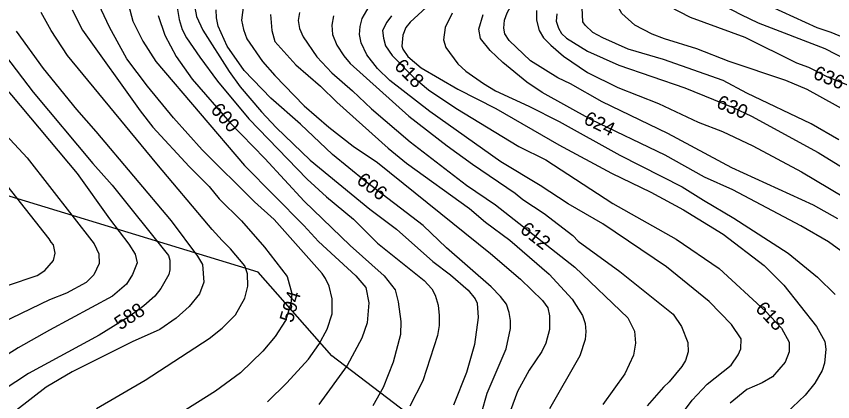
# Model space of a CAD drawing. Extents: x -709418 to -703832, y -1161719 to -1157826.
# Drawn here: x -708650.5 to -708183.3, y -1160344.3 to -1160123.5 of the extents above; entities that cross this region are included whole.
import ezdxf

# ---------------------------------------------------------------- set-up
doc = ezdxf.new("R2010")
doc.units = 0
for name, color, linetype in [('120_vrstevnice hlavní', 7, 'Continuous'), ('121_vrstevnice hlavní_popis', 7, 'Continuous'), ('122_vrstevnice základní', 7, 'Continuous'), ('606_RBC_návrh', 7, 'Continuous')]:
    doc.layers.add(name, color=color, linetype=linetype)

msp = doc.modelspace()

# ---------------------------------------------------------------- linework, layer by layer
at = {"layer": '120_vrstevnice hlavní'}
for points in [[(-708163.85, -1160141.12), (-708184.1, -1160132.87), (-708192.2, -1160130.12), (-708218.82, -1160117.98), (-708242.4, -1160104.52), (-708247.89, -1160100.04), (-708251.36, -1160096.42), (-708252.81, -1160093.82), (-708253.24, -1160088.32), (-708252.52, -1160080.22), (-708250.21, -1160068.07), (-708245.43, -1160051.87), (-708232.42, -1160023.52), (-708214.33, -1159987.07), (-708204.21, -1159962.77), (-708198.42, -1159946.57), (-708191.91, -1159933.41), (-708183.23, -1159919.09)], [(-708415.97, -1160118.55), (-708425.08, -1160126.8), (-708427.54, -1160129.83), (-708429.28, -1160134.32), (-708429.85, -1160140.54), (-708429.28, -1160142.42), (-708426.53, -1160146.47), (-708418.72, -1160153.12)], [(-708569.29, -1160123.04), (-708565.53, -1160134.32), (-708559.02, -1160146.47), (-708549.91, -1160159.49), (-708528.36, -1160184.37), (-708508.25, -1160204.91), (-708485.69, -1160229.5), (-708459.51, -1160254.81), (-708439.98, -1160272.17), (-708433.76, -1160280.27), (-708431.88, -1160287.06), (-708430.43, -1160298.35)], [(-708505.07, -1160122.46), (-708504.2, -1160131.72), (-708502.47, -1160137.94), (-708490.46, -1160151.39), (-708476.43, -1160163.54), (-708467.17, -1160172.65), (-708437.67, -1160199.12), (-708427.25, -1160207.65), (-708391.23, -1160233.55), (-708381.98, -1160241.5), (-708368.09, -1160251.77), (-708345.53, -1160271.3), (-708332.36, -1160285.62), (-708326.43, -1160294.88)], [(-708341.19, -1160122.17), (-708341.48, -1160126.22), (-708340.18, -1160130.27), (-708338.41, -1160133.4), (-708335.55, -1160136.06), (-708323.54, -1160143.43), (-708305.6, -1160151.53), (-708268, -1160164.55), (-708240.23, -1160175.69), (-708229.81, -1160180.75), (-708191.62, -1160201.58), (-708177.74, -1160210.11)], [(-708650.58, -1160132.01), (-708635.1, -1160153.41), (-708616.16, -1160176.84), (-708605.02, -1160189.43), (-708561.92, -1160240.78), (-708546.73, -1160261.03), (-708543.98, -1160265.66), (-708543.26, -1160275.93)], [(-708418.72, -1160153.12), (-708397.89, -1160165.27), (-708376.05, -1160176.41), (-708340.03, -1160197.09), (-708309.94, -1160213.44), (-708287.38, -1160224.29), (-708268.58, -1160234.41), (-708246.01, -1160248.44), (-708222.58, -1160266.24), (-708211.3, -1160277.66), (-708192.49, -1160301.24), (-708187.72, -1160309.92), (-708187.29, -1160314.26), (-708188.01, -1160322.36), (-708189.31, -1160326.41), (-708193.51, -1160333.78), (-708199, -1160340.58), (-708209.99, -1160351)], [(-708543.26, -1160275.93), (-708545.74, -1160282.61), (-708551.54, -1160289.71), (-708559.1, -1160296.56), (-708568.43, -1160302.92), (-708584.19, -1160310.06), (-708618.62, -1160327.28), (-708633.37, -1160336.1), (-708650.44, -1160349.12)], [(-708326.43, -1160294.88), (-708324.99, -1160299.5), (-708324.55, -1160304.13), (-708324.99, -1160308.76), (-708328.03, -1160318.02), (-708345.38, -1160348.39)], [(-708430.43, -1160298.35), (-708430.72, -1160305.87), (-708434.77, -1160321.78), (-708440.56, -1160336.24), (-708446.49, -1160346.8)]]:
    msp.add_lwpolyline(points, dxfattribs=at)
at = {"layer": '122_vrstevnice základní'}
for points in [[(-708324.99, -1160128.68), (-708326.29, -1160126.65), (-708326.72, -1160118.7), (-708322.09, -1160105.97), (-708283.19, -1160024.39), (-708273.06, -1160005.3), (-708264.96, -1159991.41), (-708253.24, -1159973.48), (-708243.99, -1159956.99), (-708227.35, -1159915.04), (-708205.08, -1159871.65), (-708199.44, -1159856.31), (-708195.1, -1159838.96), (-708193.94, -1159830.28), (-708193.51, -1159819), (-708194.81, -1159784.57), (-708194.52, -1159772.42), (-708191.91, -1159742.04), (-708187.14, -1159717.74), (-708182.08, -1159683.32)], [(-708177.88, -1159857.18), (-708185.84, -1159879.46), (-708196.11, -1159897.68), (-708210.72, -1159928.06), (-708226.05, -1159967.4), (-708230.82, -1159976.66), (-708253.1, -1160013.69), (-708268.29, -1160041.46), (-708273.2, -1160053.03), (-708282.17, -1160078.49), (-708286.8, -1160094.11), (-708288.1, -1160102.21), (-708287.23, -1160107.42), (-708285.64, -1160110.31), (-708282.03, -1160114.36), (-708276.97, -1160117.69), (-708264.82, -1160124.05), (-708233.57, -1160135.48), (-708204.07, -1160150.09), (-708197.12, -1160152.69), (-708186.71, -1160158.04), (-708169.35, -1160164.98)], [(-708172.68, -1160179.45), (-708197.85, -1160165.42), (-708210.14, -1160160.21), (-708242.54, -1160149.36), (-708261.06, -1160142.13), (-708279.57, -1160136.49), (-708286.51, -1160133.74), (-708296.49, -1160128.68), (-708303.87, -1160121.88), (-708306.76, -1160116.67), (-708307.78, -1160111.47), (-708307.2, -1160106.26), (-708304.59, -1160095.84), (-708300.98, -1160085.43), (-708294.61, -1160069.81), (-708275.09, -1160030.75), (-708254.69, -1159996.04), (-708236.47, -1159961.32), (-708226.77, -1159940.5), (-708219.25, -1159919.67)], [(-708130.59, -1160171.49), (-708187.58, -1160142.13), (-708225.76, -1160127.38), (-708235.74, -1160122.75), (-708249.19, -1160115.52), (-708261.05, -1160107.42), (-708266.7, -1160101.34), (-708269.01, -1160096.13), (-708269.3, -1160083.12), (-708266.41, -1160070.1), (-708257.58, -1160045.8), (-708251.36, -1160031.33), (-708246.59, -1160022.65), (-708228.22, -1159993.73)], [(-708731.58, -1160091.51), (-708729.7, -1160101.05), (-708725.65, -1160110.6), (-708715.09, -1160126.51), (-708696.29, -1160148.78), (-708644.22, -1160204.62), (-708605.89, -1160253.8), (-708603.28, -1160259.58), (-708603.14, -1160265.08), (-708606.18, -1160271.59), (-708610.52, -1160276.07), (-708621.8, -1160282.15), (-708631.49, -1160285.91), (-708658.83, -1160299.07), (-708666.64, -1160303.99), (-708679.94, -1160315.27), (-708697.16, -1160332.92), (-708715.24, -1160352.44)], [(-708180.34, -1160239.62), (-708194.23, -1160231.81), (-708241.09, -1160210.26), (-708277.54, -1160190.59), (-708315.15, -1160172.51), (-708333.38, -1160162.24), (-708340.61, -1160158.77), (-708356.23, -1160148.93), (-708368.53, -1160137.36), (-708370.86, -1160133.61), (-708371.56, -1160130.27), (-708371.13, -1160125.64), (-708369.68, -1160121.59), (-708365.2, -1160113.49), (-708352.33, -1160093.24)], [(-708506.81, -1160344.34), (-708495.67, -1160333.5), (-708483.37, -1160319.9), (-708477.3, -1160311.51), (-708472.67, -1160302.69), (-708469.78, -1160294.01), (-708469.78, -1160285.33), (-708471.47, -1160278.2), (-708473.54, -1160273.76), (-708475.42, -1160270.86), (-708502.9, -1160239.91), (-708514.18, -1160229.79), (-708544.12, -1160199.99), (-708560.61, -1160181.76), (-708575.51, -1160163.54), (-708587.23, -1160147.92), (-708597.21, -1160129.69), (-708603.28, -1160116.67)], [(-708586.22, -1160116.96), (-708583.9, -1160126.22), (-708578.11, -1160137.79), (-708570.74, -1160149.36), (-708519.97, -1160208.96), (-708485.98, -1160243.38), (-708477.59, -1160252.64), (-708456.18, -1160272.17), (-708450.39, -1160278.96), (-708448.8, -1160287.64), (-708449.67, -1160299.21), (-708452.71, -1160307.89)], [(-708558.44, -1160118.41), (-708557.29, -1160125.35), (-708555.55, -1160131.14), (-708553.09, -1160135.77), (-708545.57, -1160146.9), (-708535.3, -1160160.65), (-708517.36, -1160182.2), (-708484.1, -1160216.77)], [(-708548.32, -1160118.41), (-708547.31, -1160123.62), (-708543.83, -1160131.43), (-708528.79, -1160155.15), (-708522.43, -1160163.83), (-708510.28, -1160178.29), (-708501.74, -1160187.26), (-708482.36, -1160205.92), (-708448.18, -1160233.98), (-708432.89, -1160245.41), (-708412.06, -1160264.07)], [(-708520.4, -1160116.96), (-708521.56, -1160125.64), (-708520.55, -1160131.14), (-708518.52, -1160136.34), (-708509.7, -1160149.36), (-708502.61, -1160157.46), (-708485.69, -1160174.82), (-708471.66, -1160187.11), (-708457.77, -1160197.96), (-708443.89, -1160207.36), (-708379.08, -1160259.44), (-708362.02, -1160274.05), (-708349.43, -1160286.34), (-708346.4, -1160290.54), (-708345.38, -1160295.16), (-708345.38, -1160302.98)], [(-708271.9, -1160354.47), (-708263.8, -1160343.48), (-708255.12, -1160334.36), (-708241.38, -1160323.37), (-708237.33, -1160317.44), (-708235.89, -1160314.11), (-708235.74, -1160308.33), (-708241.24, -1160300.08), (-708253.97, -1160286.92), (-708278.41, -1160267.1), (-708314.86, -1160242.51), (-708334.68, -1160230.94), (-708350.73, -1160220.38), (-708373.3, -1160206.93), (-708413.94, -1160178), (-708436.8, -1160160.35), (-708443.89, -1160153.41), (-708449.96, -1160145.6), (-708453.14, -1160138.66), (-708454.01, -1160134.03), (-708453.72, -1160129.4), (-708452.56, -1160124.77), (-708448.51, -1160117.83)], [(-708604.59, -1160348.25), (-708576.81, -1160332.05), (-708540.22, -1160308.04), (-708532.7, -1160302.25), (-708525.03, -1160294.59), (-708519.82, -1160285.04), (-708518.09, -1160278.1), (-708518.23, -1160271.15), (-708519.82, -1160266.53), (-708527.92, -1160256.69), (-708532.7, -1160252.06), (-708538.34, -1160245.7), (-708540.51, -1160243.24), (-708570.07, -1160208.14), (-708621.22, -1160145.89), (-708630.62, -1160131.72), (-708636.26, -1160121.3)], [(-708618.61, -1160119.85), (-708612.69, -1160131.43), (-708579.71, -1160177.71), (-708572.33, -1160186.97), (-708551.65, -1160209.54), (-708540.22, -1160221.11), (-708534.43, -1160228.05), (-708521.7, -1160240.63), (-708508.54, -1160255.82), (-708495.52, -1160272.6), (-708492.92, -1160282.44)], [(-708504.78, -1160170.34), (-708520.11, -1160154.57), (-708529.8, -1160140.68), (-708535.01, -1160129.11), (-708536.02, -1160124.48), (-708536.17, -1160119.85)], [(-708488.44, -1160121.3), (-708489.3, -1160125.93), (-708488.44, -1160130.56), (-708486.27, -1160135.19), (-708478.6, -1160146.76), (-708469.92, -1160155.87), (-708458.06, -1160166.14), (-708447.21, -1160176.56), (-708425.08, -1160195.5), (-708392.83, -1160220.24), (-708376.19, -1160231.52)], [(-708469.05, -1160123.33), (-708469.92, -1160128.53), (-708469.49, -1160134.03), (-708467.03, -1160140.11), (-708463.12, -1160146.18), (-708459.51, -1160150.52), (-708425.95, -1160180.75)], [(-708435.79, -1160123.33), (-708438.53, -1160126.8), (-708440.85, -1160131.72), (-708440.41, -1160136.06), (-708439.26, -1160140.4), (-708435.35, -1160146.04), (-708423.06, -1160158.62), (-708414.67, -1160165.56), (-708399.05, -1160176.12), (-708362.88, -1160198.11), (-708347.55, -1160205.77), (-708309.08, -1160230.8), (-708272.92, -1160251.19), (-708248.33, -1160267.97), (-708221.71, -1160292.42)], [(-708401.07, -1160121.74), (-708404.98, -1160129.98), (-708405.99, -1160136.92), (-708404.69, -1160141.41), (-708397.74, -1160150.81), (-708393.26, -1160154.86), (-708383.13, -1160162.09), (-708376.19, -1160166.14), (-708357.1, -1160174.97), (-708339.74, -1160183.79)], [(-708385.86, -1160130.86), (-708383.28, -1160122.46)], [(-708352.76, -1160120.15), (-708352.76, -1160125.64), (-708351.31, -1160131.72), (-708348.71, -1160135.77), (-708344.66, -1160140.11), (-708337.28, -1160146.32), (-708323.54, -1160155.73), (-708306.18, -1160164.26), (-708283.04, -1160173.52), (-708260.19, -1160184.22), (-708246.3, -1160189.43), (-708228.94, -1160197.67), (-708201.17, -1160212.57), (-708168.19, -1160232.24)], [(-708688.33, -1160127.09), (-708675.9, -1160142.71), (-708653.33, -1160168.75), (-708615.72, -1160213.58), (-708597.21, -1160239.62), (-708586.07, -1160254.08), (-708582.45, -1160259.87), (-708581.44, -1160264.79), (-708584.05, -1160271.44), (-708587.52, -1160277.08), (-708595.47, -1160283.88), (-708631.49, -1160303.41), (-708649.43, -1160313.53), (-708658.83, -1160319.47), (-708666.49, -1160325.54), (-708677.49, -1160336.1), (-708710.32, -1160370.38)], [(-708179.76, -1160194.35), (-708195.68, -1160185.09), (-708232.42, -1160167.59), (-708246.01, -1160160.35), (-708280.15, -1160148.35), (-708300.4, -1160142.28), (-708314.86, -1160135.91), (-708320.5, -1160132.87), (-708324.99, -1160128.68)], [(-708172.39, -1160262.48), (-708185.69, -1160252.78), (-708201.46, -1160243.53), (-708240.52, -1160222.99), (-708256.72, -1160215.76), (-708279.14, -1160203.17), (-708321.23, -1160182.78), (-708349.58, -1160167.15), (-708358.26, -1160161.22), (-708372, -1160149.94), (-708379.31, -1160143.09), (-708384.85, -1160136.24), (-708385.86, -1160130.86)], [(-708656.8, -1160146.18), (-708640.89, -1160167.01), (-708606.75, -1160207.8), (-708595.62, -1160220.24)], [(-708384.29, -1160351), (-708380.96, -1160339.43), (-708370.12, -1160313.97), (-708367.66, -1160302.4), (-708367.66, -1160297.77), (-708368.38, -1160293.14), (-708369.97, -1160288.51), (-708373.44, -1160284.03), (-708378.8, -1160278.53), (-708404.25, -1160256.26), (-708417.7, -1160243.38), (-708450.83, -1160217.92), (-708469.49, -1160202.74), (-708487.86, -1160185.38), (-708504.78, -1160170.34)], [(-708425.95, -1160180.75), (-708403.96, -1160197.82), (-708389.5, -1160208.23), (-708365.05, -1160224.87), (-708360.57, -1160228.48), (-708348.42, -1160236.44), (-708332.08, -1160249.17), (-708328.89, -1160252.35), (-708305.03, -1160269.71), (-708274.65, -1160294.15), (-708269.73, -1160301.24), (-708266.12, -1160310.5), (-708265.97, -1160315.7), (-708267.56, -1160320.77), (-708269.59, -1160324.24), (-708276.82, -1160332.92), (-708280.15, -1160335.95), (-708289.4, -1160346.66)], [(-708339.74, -1160183.79), (-708305.03, -1160203.03), (-708269.44, -1160221.25), (-708257.29, -1160228.77), (-708239.94, -1160239.19), (-708208.69, -1160259.29), (-708191.91, -1160273.03), (-708181.93, -1160283.01)], [(-708655.64, -1160277.81), (-708638.58, -1160272.02), (-708634.24, -1160269.13), (-708629.17, -1160263.49), (-708628.31, -1160259.15), (-708629.32, -1160254.52), (-708630.48, -1160252.93), (-708631.78, -1160251.05), (-708674.59, -1160196.81)], [(-708484.1, -1160216.77), (-708473, -1160227.04), (-708457.63, -1160239.77), (-708443.74, -1160253.51), (-708417.13, -1160274.91), (-708412.64, -1160279.69), (-708410.76, -1160283.3), (-708409.03, -1160289.09), (-708408.45, -1160294.88), (-708408.59, -1160300.66), (-708409.46, -1160306.45), (-708417.85, -1160332.48), (-708425.22, -1160346.95)], [(-708595.62, -1160220.24), (-708563.51, -1160260.59), (-708562.64, -1160263.2), (-708562.64, -1160268.84), (-708563.22, -1160271.44), (-708567.85, -1160279.54), (-708571.32, -1160283.88), (-708577.54, -1160289.38), (-708585.64, -1160295.31), (-708603.14, -1160306.16), (-708643.49, -1160328.14), (-708658.1, -1160337.69), (-708669.53, -1160347.09)], [(-708376.19, -1160231.52), (-708330.77, -1160267.25), (-708300.54, -1160296.32), (-708296.78, -1160303.84), (-708296.06, -1160310.79), (-708297.22, -1160317.73), (-708302.28, -1160328.43), (-708314.86, -1160345.93)], [(-708412.06, -1160264.07), (-708402.08, -1160271.59), (-708391.96, -1160280.41), (-708387.91, -1160285.47), (-708386.75, -1160287.93), (-708386.17, -1160296.03), (-708388.2, -1160311.65), (-708392.83, -1160327.56), (-708400.35, -1160346.37)], [(-708492.92, -1160282.44), (-708493.35, -1160288.22), (-708496.54, -1160297.77), (-708502.32, -1160307.03), (-708509.41, -1160315.41), (-708522.28, -1160327.71), (-708536.46, -1160338.27), (-708592.58, -1160373.71)], [(-708221.71, -1160292.42), (-708212.6, -1160302.25), (-708208.26, -1160310.21), (-708208.26, -1160315.7), (-708210.43, -1160321.78), (-708217.66, -1160330.02), (-708223.74, -1160333.5), (-708232.42, -1160337.26), (-708241.96, -1160345.21)], [(-708345.38, -1160302.98), (-708347.41, -1160310.79), (-708349.72, -1160315.56), (-708356.95, -1160326.26), (-708363.75, -1160338.56), (-708369.1, -1160353.02)], [(-708452.71, -1160307.89), (-708461.1, -1160323.51), (-708477.44, -1160345.93)]]:
    msp.add_lwpolyline(points, dxfattribs=at)
at = {"layer": '606_RBC_návrh'}
msp.add_lwpolyline([(-708179, -1160478.74), (-708234.99, -1160497.4), (-708469.98, -1160318), (-708512.17, -1160270.15), (-708708.54, -1160210.13), (-708756.41, -1160202.02), (-708819.7, -1160215.81), (-708991.72, -1160287.99), (-709033.11, -1160299.35)], dxfattribs=at)

# ---------------------------------------------------------------- texts
at = {"layer": '121_vrstevnice hlavní_popis'}
for s, rotation, p in [('618', 315.2678, (-708434.71, -1160152.68)), ('636', 337.6531, (-708195.07, -1160158.89)), ('630', 336.725, (-708250.44, -1160175.59)), ('600', 311.5534, (-708539.8, -1160177.44)), ('624', 334.0988, (-708326.39, -1160184.69)), ('606', 322.6187, (-708456.37, -1160218.69)), ('612', 321.8932, (-708362.82, -1160246.86)), ('594', 74.2452, (-708492.38, -1160299.49)), ('618', 314.1696, (-708228.01, -1160291.55)), ('588', 33.4182, (-708591.05, -1160303.61))]:
    msp.add_text(s, height=8, rotation=rotation, dxfattribs=at).set_placement(p)

doc.saveas('drawing.dxf')
